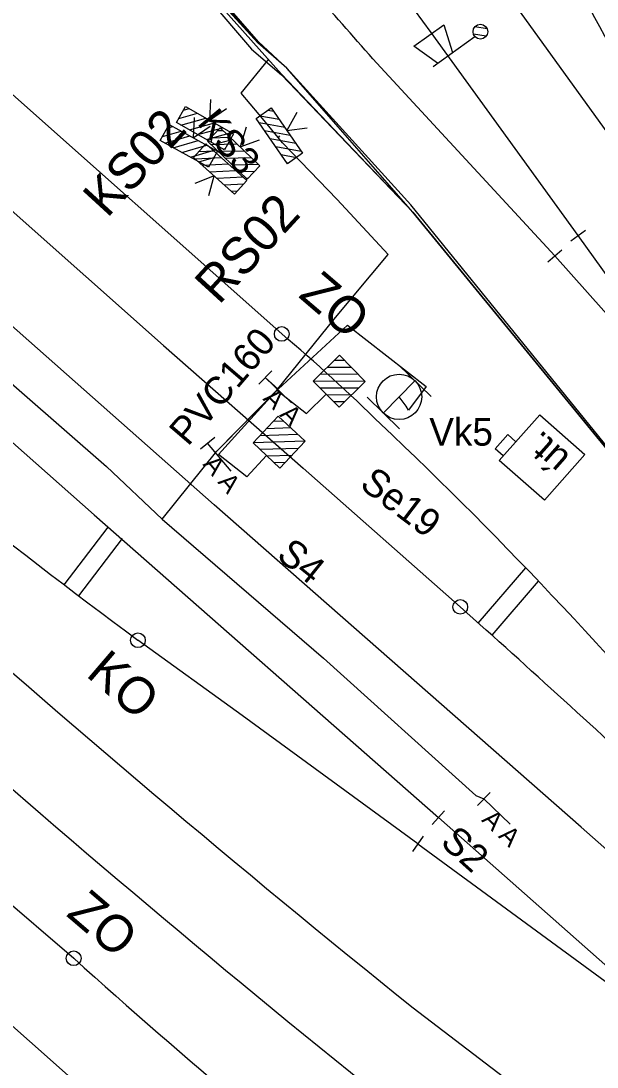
# Model space of a CAD drawing. Extents: x -496570 to -495506, y -1089156 to -1088046.
# Drawn here: x -496096.7 to -496065.3, y -1088542 to -1088485 of the extents above; entities that cross this region are included whole.
import ezdxf

# ---------------------------------------------------------------- set-up
doc = ezdxf.new("R2010")
doc.units = 0
for name, color, linetype in [('11', 7, 'Continuous'), ('14', 7, 'Continuous'), ('15', 7, 'Continuous'), ('20', 7, 'Continuous'), ('27', 7, 'Continuous'), ('39', 7, 'Continuous'), ('54', 7, 'Continuous'), ('PŘÍSTUPOVÉ_CESTY', 7, 'Continuous'), ('PŮVODNÍ_NÁVRH', 7, 'Continuous'), ('SEE', 7, 'Continuous')]:
    doc.layers.add(name, color=color, linetype=linetype)

msp = doc.modelspace()

# ---------------------------------------------------------------- linework, layer by layer
at = {"layer": '11'}
for points in [[(-496094.318, -1088515.702), (-496091.937, -1088512.569)], [(-496093.522, -1088516.306), (-496091.153, -1088513.188)], [(-496071.793, -1088517.787), (-496069.203, -1088514.783)], [(-496071.035, -1088518.441), (-496068.507, -1088515.509)]]:
    msp.add_lwpolyline(points, dxfattribs=at)
at = {"layer": '14'}
msp.add_line((-496075.335, -1088538.747), (-496053.911, -1088555.054), dxfattribs=at)
for points in [[(-496500.326, -1088150.883), (-496478.319, -1088170.391), (-496459.205, -1088187.309), (-496440.603, -1088203.768), (-496419.398, -1088222.532), (-496401.337, -1088238.524), (-496381.863, -1088255.763), (-496363.496, -1088272.022), (-496344.908, -1088288.479), (-496325.602, -1088305.577), (-496305.115, -1088323.698), (-496285.279, -1088341.274), (-496267.778, -1088356.78), (-496248.642, -1088373.733), (-496220.391, -1088398.759), (-496201.351, -1088415.62), (-496182.974, -1088431.889), (-496164.259, -1088448.462), (-496145.687, -1088464.902), (-496132.984, -1088476.226), (-496115.09, -1088492.058), (-496092.682, -1088511.89), (-496073.961, -1088528.378)], [(-496036.118, -1088555.5), (-496048.975, -1088544.1), (-496066.196, -1088528.906), (-496086.152, -1088511.349), (-496104.929, -1088494.746), (-496123.588, -1088478.229), (-496142.293, -1088461.701), (-496160.965, -1088445.175), (-496179.891, -1088428.396), (-496198.214, -1088412.189), (-496217.292, -1088395.311), (-496245.811, -1088370.064), (-496264.918, -1088353.145), (-496281.988, -1088338.018), (-496302.247, -1088320.079), (-496322.57, -1088302.076), (-496341.966, -1088284.907), (-496360.552, -1088268.447), (-496378.713, -1088252.378), (-496398.4, -1088234.928), (-496416.447, -1088218.945), (-496437.668, -1088200.162), (-496456.103, -1088183.845), (-496474.042, -1088168.071)], [(-496082.486, -1088502.043), (-496098.63, -1088487.696), (-496117.358, -1088471.138), (-496136.056, -1088454.602), (-496154.785, -1088438.063), (-496173.551, -1088421.521), (-496192.303, -1088405.013), (-496211.05, -1088388.494), (-496229.814, -1088371.969), (-496241.71, -1088361.483), (-496259.312, -1088345.98), (-496335.952, -1088278.18), (-496354.664, -1088261.608), (-496372.853, -1088245.502), (-496392.083, -1088228.459), (-496410.817, -1088211.882), (-496431.795, -1088193.31), (-496448.334, -1088178.663)], [(-496419.776, -1088210.17), (-496413.73, -1088215.561), (-496395.384, -1088231.799), (-496375.938, -1088249.024), (-496357.661, -1088265.193), (-496339.088, -1088281.642), (-496320.817, -1088297.785), (-496278.447, -1088335.251), (-496262.212, -1088349.594), (-496242.734, -1088366.795), (-496214.147, -1088392.048), (-496195.339, -1088408.643), (-496176.8, -1088425.002), (-496157.997, -1088441.59), (-496139.148, -1088458.239), (-496120.509, -1088474.69), (-496101.775, -1088491.246), (-496088.913, -1088502.664), (-496081.326, -1088509.353), (-496072.768, -1088516.905)], [(-496183.115, -1088457.032), (-496166.27, -1088472.019), (-496131.046, -1088503.215), (-496098.048, -1088532.397), (-496093.805, -1088536.044)], [(-496093.621, -1088542.853), (-496114.06, -1088524.717), (-496138.8, -1088502.766), (-496174.593, -1088471.013)], [(-496011.29, -1088565.037), (-496022.068, -1088550.141), (-496029.461, -1088539.924), (-496036.884, -1088529.665), (-496046.952, -1088515.759), (-496054.33, -1088505.532), (-496061.713, -1088495.299), (-496072.458, -1088480.37)], [(-496051.597, -1088517.251), (-496056.967, -1088509.766), (-496066.353, -1088496.683), (-496074.345, -1088485.622)], [(-496056.967, -1088509.766), (-496067.626, -1088497.784), (-496077.528, -1088487.052)], [(-496075.077, -1088529.806), (-496084.64, -1088522.821), (-496090.308, -1088518.722)]]:
    msp.add_lwpolyline(points, dxfattribs=at)
for centre in [(-496082.486, -1088502.043), (-496072.768, -1088516.905), (-496090.308, -1088518.722), (-496093.805, -1088536.044)]:
    msp.add_circle(centre, 0.4, dxfattribs=at)
for centre, major_axis, ratio, start_param, end_param in [((-495904.217, -1088267.163), (240.608, -200.87), 0.998317, 4.684202, 4.771008), ((-496141.513, -1088572.207), (70.842, -58.275), 0.999559, 1.480233, 1.559775), ((-496231.127, -1088670.242), (-155.662, 162.098), 0.998824, 4.636619, 4.761735), ((-495616.903, -1087969.14), (-563.673, 468.202), 0.997828, 1.536282, 1.586227), ((-496676.928, -1089192.103), (-679.187, 608.851), 0.993311, 4.696651, 4.713299), ((-495661.207, -1088025.176), (-508.889, 430.705), 0.996869, 1.547662, 1.600405), ((-495832.376, -1088245.472), (-305.585, 244.796), 0.998266, 1.513638, 1.639034)]:
    msp.add_ellipse(centre, major_axis=major_axis, ratio=ratio, start_param=start_param, end_param=end_param, dxfattribs=at)
for points in [[(-496060.305, -1088494.392), (-496069.107, -1088478.342), (-496082.819, -1088457.845), (-496098.833, -1088439.695), (-496101.304, -1088437.234), (-496120.979, -1088419.513)], [(-496074.345, -1088485.622), (-496089.123, -1088466.132), (-496102.218, -1088451.049), (-496125.082, -1088429.936)], [(-496077.528, -1088487.052), (-496084.13, -1088479.499), (-496092.21, -1088470.077), (-496106.458, -1088454.308), (-496128.434, -1088433.508)], [(-496076.529, -1088566.028), (-496092.943, -1088555.668), (-496104.359, -1088548.012), (-496117.617, -1088537.987)], [(-496076.075, -1088564.025), (-496087.586, -1088554.298), (-496104.138, -1088539.66)], [(-496063.641, -1088579.453), (-496076.368, -1088572.308), (-496088.307, -1088565.016), (-496095.758, -1088560.128), (-496107.252, -1088552.116), (-496120.36, -1088541.773)]]:
    msp.add_spline(points, degree=3, dxfattribs=at)
at = {"layer": '15'}
for p, q in [((-496078.69, -1088503.871), (-496080.018, -1088503.863)), ((-496079.062, -1088503.494), (-496079.64, -1088503.491)), ((-496076.122, -1088503.728), (-496074.358, -1088505.448)), ((-496078.317, -1088504.249), (-496080.395, -1088504.236)), ((-496077.944, -1088504.626), (-496080.773, -1088504.608)), ((-496078.321, -1088504.999), (-496080.4, -1088504.986)), ((-496076.96, -1088506.352), (-496075.24, -1088504.588)), ((-496078.699, -1088505.372), (-496080.027, -1088505.363)), ((-496077.842, -1088505.492), (-496076.078, -1088507.212)), ((-496079.076, -1088505.744), (-496079.655, -1088505.741)), ((-496081.987, -1088507.159), (-496083.315, -1088507.202)), ((-496082.374, -1088506.796), (-496082.952, -1088506.815)), ((-496081.6, -1088507.522), (-496083.678, -1088507.59)), ((-496081.213, -1088507.884), (-496084.04, -1088507.976)), ((-496081.575, -1088508.271), (-496083.653, -1088508.339)), ((-496081.938, -1088508.658), (-496083.265, -1088508.702)), ((-496082.301, -1088509.045), (-496082.879, -1088509.064))]:
    msp.add_line(p, q, dxfattribs=at)
for points in [[(-496079.367, -1088506.032), (-496080.773, -1088504.608), (-496079.349, -1088503.203), (-496077.944, -1088504.626)], [(-496079.367, -1088506.032), (-496080.773, -1088504.608), (-496079.349, -1088503.203), (-496077.944, -1088504.626)], [(-496082.58, -1088509.344), (-496084.04, -1088507.976), (-496082.673, -1088506.517), (-496081.213, -1088507.884)], [(-496082.58, -1088509.344), (-496084.04, -1088507.976), (-496082.673, -1088506.517), (-496081.213, -1088507.884)]]:
    msp.add_lwpolyline(points, close=True, dxfattribs=at)
for points in [[(-496079.367, -1088506.032), (-496080.773, -1088504.608), (-496079.349, -1088503.203), (-496077.944, -1088504.626), (-496079.367, -1088506.032)], [(-496079.367, -1088506.032), (-496080.773, -1088504.608), (-496079.349, -1088503.203), (-496077.944, -1088504.626), (-496079.367, -1088506.032)], [(-496082.58, -1088509.344), (-496084.04, -1088507.976), (-496082.673, -1088506.517), (-496081.213, -1088507.884), (-496082.58, -1088509.344)], [(-496082.58, -1088509.344), (-496084.04, -1088507.976), (-496082.673, -1088506.517), (-496081.213, -1088507.884), (-496082.58, -1088509.344)]]:
    msp.add_lwpolyline(points, dxfattribs=at)
msp.add_circle((-496076.097, -1088505.466), 1.232, dxfattribs=at)
at = {"layer": '20'}
for p, q in [((-496083.031, -1088504.057), (-496083.725, -1088504.777)), ((-496081.954, -1088505.792), (-496083.378, -1088504.417)), ((-496086.132, -1088507.672), (-496086.898, -1088508.314)), ((-496085.242, -1088509.51), (-496086.515, -1088507.993)), ((-496071.135, -1088527.006), (-496071.829, -1088527.726)), ((-496070.055, -1088528.738), (-496071.482, -1088527.366))]:
    msp.add_line(p, q, dxfattribs=at)
at = {"layer": '27'}
for p, q in [((-496066.759, -1088496.975), (-496065.947, -1088496.391)), ((-496068, -1088498.116), (-496067.252, -1088497.452)), ((-496073.63, -1088528.003), (-496074.292, -1088528.753)), ((-496074.794, -1088529.394), (-496075.36, -1088530.218))]:
    msp.add_line(p, q, dxfattribs=at)
for points in [[(-496051.597, -1088517.251), (-496056.967, -1088509.766), (-496066.353, -1088496.683)], [(-496056.967, -1088509.766), (-496067.626, -1088497.784)], [(-496048.752, -1088550.648), (-496058.972, -1088541.619), (-496073.961, -1088528.378)], [(-496075.077, -1088529.806), (-496058.972, -1088541.619)]]:
    msp.add_lwpolyline(points, dxfattribs=at)
at = {"layer": '39'}
for points in [[(-496070.65, -1088508.925), (-496068.443, -1088506.439), (-496065.983, -1088508.614), (-496068.19, -1088511.1), (-496070.65, -1088508.925)], [(-496070.433, -1088508.681), (-496070.872, -1088508.291), (-496070.19, -1088507.524), (-496069.752, -1088507.913)]]:
    msp.add_lwpolyline(points, dxfattribs=at)
at = {"layer": '54'}
for p, q in [((-496083.667, -1088490.157), (-496082.626, -1088490.347)), ((-496083.231, -1088489.856), (-496082.928, -1088489.911)), ((-496083.716, -1088490.53), (-496082.324, -1088490.784)), ((-496083.414, -1088490.966), (-496082.023, -1088491.22)), ((-496082.61, -1088491.25), (-496082.682, -1088491.347)), ((-496083.113, -1088491.402), (-496081.722, -1088491.656)), ((-496082.811, -1088491.839), (-496081.42, -1088492.093)), ((-496082.51, -1088492.275), (-496081.675, -1088492.427)), ((-496082.208, -1088492.711), (-496082.111, -1088492.728)), ((-496082.671, -1088505.05), (-496083.378, -1088504.417))]:
    msp.add_line(p, q, dxfattribs=at)
for points in [[(-496035.05, -1088546.1), (-496051.31, -1088524.79), (-496051.95, -1088524), (-496075.46, -1088495.01), (-496082.21, -1088487.56), (-496083.74, -1088486.13), (-496115.78, -1088449.34), (-496116.666, -1088448.476), (-496129.8, -1088436.28), (-496168.994, -1088401.872), (-496172.14, -1088399.257), (-496208.919, -1088366.316), (-496218.168, -1088358.05), (-496219.89, -1088357.07), (-496221.818, -1088357.316), (-496227.949, -1088364.044), (-496231.283, -1088367.587), (-496235.293, -1088372.311), (-496239.162, -1088376.183), (-496245.965, -1088384.343), (-496248.182, -1088386.654), (-496249.196, -1088385.882), (-496252.528, -1088385.701), (-496270.673, -1088369.666)], [(-496249.196, -1088385.882), (-496248.182, -1088386.654), (-496245.965, -1088384.343), (-496239.162, -1088376.183), (-496235.293, -1088372.311), (-496231.283, -1088367.587), (-496227.949, -1088364.044), (-496221.818, -1088357.316), (-496219.9, -1088357.08), (-496218.168, -1088358.05), (-496208.919, -1088366.316), (-496172.14, -1088399.257), (-496168.994, -1088401.872), (-496129.8, -1088436.28), (-496116.666, -1088448.476), (-496115.78, -1088449.34), (-496093.74, -1088475.27), (-496082.49, -1088487.89), (-496075.35, -1088495.41), (-496051.95, -1088524), (-496051.31, -1088524.79), (-496034.93, -1088546.87)], [(-496035.05, -1088546.1), (-496051.01, -1088524.68), (-496051.95, -1088524), (-496075.35, -1088495.41), (-496082.21, -1088487.56), (-496083.74, -1088486.13), (-496093.74, -1088475.27), (-496115.78, -1088449.34)], [(-496083.31, -1088508.66), (-496084.38, -1088509.83), (-496085.93, -1088508.6), (-496082.75, -1088505.1), (-496079.56, -1088501.15), (-496076.69, -1088497.71), (-496079.47, -1088494.72), (-496082.44, -1088491.64), (-496082.682, -1088491.347), (-496083.72, -1088490.09), (-496084.7, -1088488.92), (-496083.179, -1088487.071)], [(-496083.052, -1088489.732), (-496081.346, -1088492.2), (-496082.168, -1088492.768), (-496083.874, -1088490.3), (-496083.052, -1088489.732)], [(-496081.66, -1088489.986), (-496082.199, -1088490.966), (-496081.092, -1088490.808)], [(-496098.957, -1088503.214), (-496092.024, -1088509.261), (-496088.984, -1088512.119), (-496086.022, -1088508.433), (-496082.671, -1088505.05), (-496078.909, -1088501.569), (-496074.62, -1088504.91), (-496075.59, -1088506.19), (-496075.72, -1088505.97), (-496076.1, -1088505.47)], [(-496082.75, -1088505.1), (-496081.14, -1088506.37), (-496080.07, -1088505.32)], [(-496088.984, -1088512.119), (-496080.205, -1088519.699), (-496071.927, -1088527.178), (-496071.482, -1088527.366)]]:
    msp.add_lwpolyline(points, dxfattribs=at)
msp.add_lwpolyline([(-496083.052, -1088489.732), (-496081.346, -1088492.2), (-496082.168, -1088492.768), (-496083.874, -1088490.3)], close=True, dxfattribs=at)
at = {"layer": 'PŘÍSTUPOVÉ_CESTY'}
for p, q in [((-496075.288, -1088486.374), (-496073.667, -1088485.203)), ((-496073.667, -1088485.203), (-496073.194, -1088486.711)), ((-496071.303, -1088485.43), (-496071.976, -1088485.322)), ((-496074.248, -1088487.472), (-496071.983, -1088485.833)), ((-496071.358, -1088485.827), (-496072.045, -1088485.716)), ((-496074.004, -1088487.298), (-496075.288, -1088486.374)), ((-496088.087, -1088490.306), (-496087.067, -1088490.024)), ((-496087.826, -1088489.845), (-496087.528, -1088489.763)), ((-496088.718, -1088490.829), (-496088.421, -1088490.743)), ((-496087.969, -1088490.662), (-496086.606, -1088490.286)), ((-496087.508, -1088490.924), (-496086.145, -1088490.548)), ((-496088.973, -1088491.293), (-496087.957, -1088490.999)), ((-496088.851, -1088491.649), (-496087.492, -1088491.255)), ((-496087.047, -1088491.185), (-496085.684, -1088490.809)), ((-496086.585, -1088491.447), (-496085.222, -1088491.071)), ((-496086.355, -1088491.352), (-496085.297, -1088491.329)), ((-496085.988, -1088490.969), (-496085.68, -1088490.962)), ((-496088.387, -1088491.904), (-496087.028, -1088491.511)), ((-496087.922, -1088492.16), (-496086.564, -1088491.767)), ((-496086.56, -1088491.732), (-496086.659, -1088491.738)), ((-496086.328, -1088491.727), (-496084.914, -1088491.696)), ((-496086.124, -1088491.709), (-496085.306, -1088491.483)), ((-496087.457, -1088492.416), (-496086.099, -1088492.023)), ((-496085.771, -1088492.441), (-496087.183, -1088492.517)), ((-496086.165, -1088492.087), (-496087.013, -1088492.132)), ((-496086.993, -1088492.672), (-496086.178, -1088492.436)), ((-496085.945, -1088492.093), (-496084.531, -1088492.063)), ((-496085.663, -1088491.97), (-496085.567, -1088491.944)), ((-496085.562, -1088492.46), (-496084.148, -1088492.429)), ((-496085.376, -1088492.796), (-496086.788, -1088492.871)), ((-496086.529, -1088492.928), (-496086.434, -1088492.901)), ((-496085.179, -1088492.827), (-496083.765, -1088492.796)), ((-496084.982, -1088493.15), (-496086.394, -1088493.225)), ((-496084.588, -1088493.504), (-496086, -1088493.58)), ((-496084.796, -1088493.194), (-496083.948, -1088493.175)), ((-496084.413, -1088493.56), (-496084.314, -1088493.558)), ((-496084.548, -1088493.878), (-496085.605, -1088493.934)), ((-496084.903, -1088494.272), (-496085.21, -1088494.289))]:
    msp.add_line(p, q, dxfattribs=at)
for points in [[(-496086.355, -1088489.279), (-496086.413, -1088490.395), (-496085.485, -1088489.772)], [(-496087.718, -1088489.655), (-496085.109, -1088491.135), (-496085.602, -1088492.005), (-496088.211, -1088490.525), (-496087.718, -1088489.655)], [(-496088.612, -1088490.638), (-496085.985, -1088492.086), (-496086.468, -1088492.962), (-496089.095, -1088491.514), (-496088.612, -1088490.638)], [(-496087.254, -1088490.245), (-496087.299, -1088491.362), (-496086.378, -1088490.728)], [(-496085.837, -1088490.811), (-496083.671, -1088492.886), (-496084.363, -1088493.609), (-496086.529, -1088491.534), (-496085.837, -1088490.811)], [(-496084.424, -1088490.781), (-496084.754, -1088491.849), (-496083.701, -1088491.473)], [(-496085.048, -1088494.434), (-496087.28, -1088492.43), (-496086.612, -1088491.686), (-496084.38, -1088493.69), (-496085.048, -1088494.434)], [(-496086.46, -1088494.51), (-496086.164, -1088493.432), (-496087.204, -1088493.842)]]:
    msp.add_lwpolyline(points, dxfattribs=at)
for points in [[(-496087.718, -1088489.655), (-496085.109, -1088491.135), (-496085.602, -1088492.005), (-496088.211, -1088490.525)], [(-496088.612, -1088490.638), (-496085.985, -1088492.086), (-496086.468, -1088492.962), (-496089.095, -1088491.514)], [(-496085.837, -1088490.811), (-496083.671, -1088492.886), (-496084.363, -1088493.609), (-496086.529, -1088491.534)], [(-496085.048, -1088494.434), (-496087.28, -1088492.43), (-496086.612, -1088491.686), (-496084.38, -1088493.69)]]:
    msp.add_lwpolyline(points, close=True, dxfattribs=at)
msp.add_circle((-496071.672, -1088485.58), 0.401, dxfattribs=at)
msp.add_circle((-496071.672, -1088485.58), 0.401, dxfattribs=at)
at = {"layer": 'PŮVODNÍ_NÁVRH'}
for points in [[(-496015.829, -1088567.72), (-496024.83, -1088557.73), (-496034.93, -1088546.87), (-496051.31, -1088524.79), (-496051.95, -1088524), (-496075.35, -1088495.41), (-496082.21, -1088487.56), (-496083.78, -1088486.19), (-496093.74, -1088475.27), (-496115.78, -1088449.34)], [(-496088.984, -1088512.119), (-496086.022, -1088508.433), (-496082.75, -1088505.1), (-496079.56, -1088501.15)]]:
    msp.add_lwpolyline(points, dxfattribs=at)
at = {"layer": 'SEE'}
msp.add_lwpolyline([(-496115.78, -1088449.34), (-496093.74, -1088475.27), (-496084.13, -1088486.54), (-496082.5, -1088487.93), (-496075.35, -1088495.41), (-496051.95, -1088524), (-496051.31, -1088524.79), (-496034.93, -1088546.87)], dxfattribs=at)
msp.add_lwpolyline([(-496115.78, -1088449.34), (-496093.74, -1088475.27), (-496084.13, -1088486.54), (-496082.5, -1088487.93), (-496075.35, -1088495.41), (-496051.95, -1088524), (-496051.31, -1088524.79), (-496034.93, -1088546.87)], dxfattribs=at)

# ---------------------------------------------------------------- texts
at = {"layer": '14'}
for s, p in [('ZO', (-496081.63, -1088499.998)), ('KO', (-496093.197, -1088520.637)), ('ZO', (-496094.264, -1088533.693))]:
    msp.add_text(s, height=2, rotation=319.4182, dxfattribs=at).set_placement(p)
at = {"layer": '15'}
msp.add_text('Vk5', height=1.5, dxfattribs=at).set_placement((-496074.452, -1088508.124))
at = {"layer": '20'}
for s, height, rotation, p in [('  A A', 1, 315.9997, (-496084.086, -1088505.088)), ('  A A', 1, 309.9977, (-496087.289, -1088508.586)), ('Se19', 1.5, 322.7792, (-496078.309, -1088510.373)), ('S4', 1.5, 321.1574, (-496082.832, -1088514.221)), ('  A A', 1, 316.1313, (-496072.188, -1088528.038)), ('S2', 1.5, 317.9048, (-496073.915, -1088529.816))]:
    msp.add_text(s, height=height, rotation=rotation, dxfattribs=at).set_placement(p)
at = {"layer": '39'}
msp.add_text('út.', height=1.5, rotation=138.5186, dxfattribs=at).set_placement((-496066.722, -1088508.694))
at = {"layer": '54'}
for s, rotation, p in [('KS3', 309.6973, (-496087.13, -1088490.578)), ('PVC160', 49.4179, (-496087.59, -1088508.205))]:
    msp.add_text(s, height=1.5, rotation=rotation, dxfattribs=at).set_placement(p)
at = {"layer": 'PŘÍSTUPOVÉ_CESTY'}
for s, p in [('KS02', (-496091.983, -1088495.771)), ('RS02', (-496085.903, -1088500.502))]:
    msp.add_text(s, height=2, rotation=47.4822, dxfattribs=at).set_placement(p)

doc.saveas('drawing.dxf')
